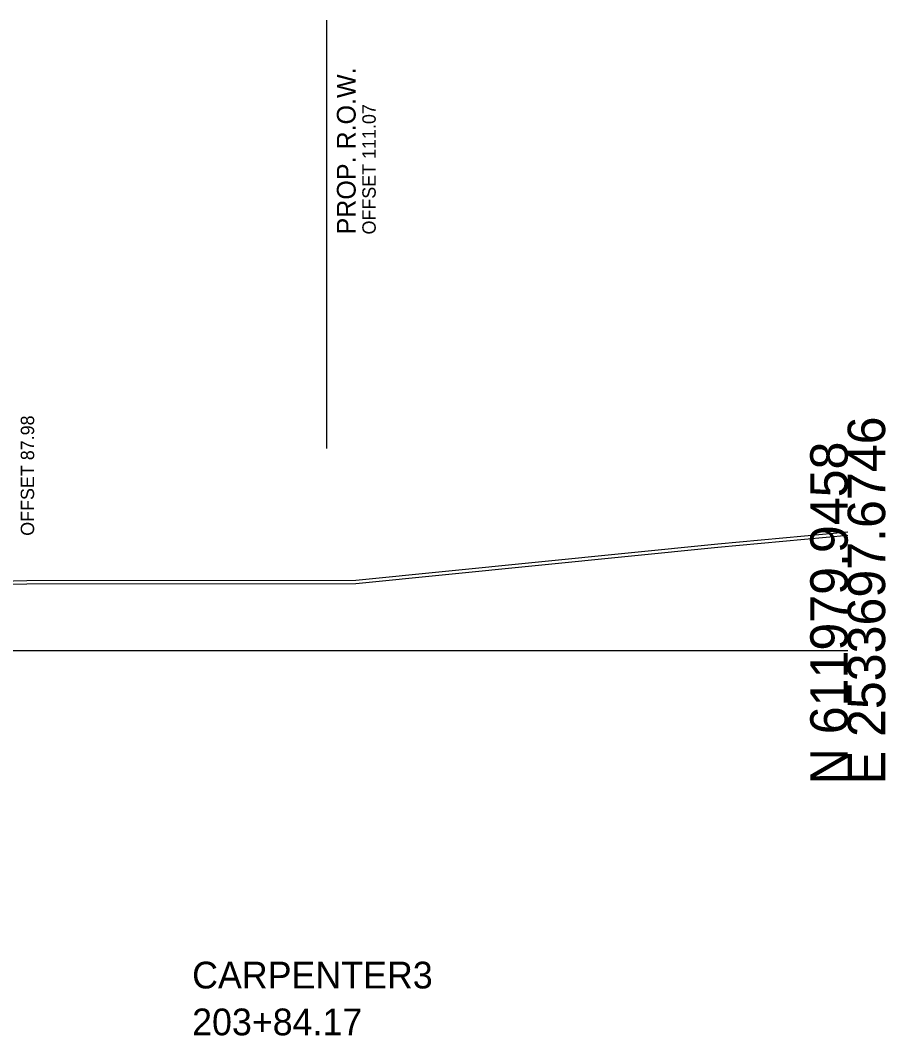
# Model space of a CAD drawing. Extents: x -120 to 2876, y -25 to 8560.
# Drawn here: x 1538.2 to 1602.8, y 1471.2 to 1547.1 of the extents above; entities that cross this region are included whole.
import ezdxf

# ---------------------------------------------------------------- set-up
doc = ezdxf.new("R2010")
doc.units = 0
for name, color, linetype in [('DESIGN - ROW - Right-of-Way and Easement Labels', 7, 'Continuous'), ('DESIGN - ROW - Right-of-Way Linework', 7, 'Continuous'), ('DESIGN - SHEET - Light Grid', 7, 'Continuous'), ('DESIGN - TYPICAL - Slope Tie Text', 7, 'Continuous'), ('DESIGN - TYPICAL - Warning Text', 7, 'Continuous'), ('SURVEY - GROUND - Bottom of Topsoil Layer', 7, 'Continuous'), ('SURVEY - GROUND - Top of Ground', 7, 'Continuous')]:
    doc.layers.add(name, color=color, linetype=linetype)

msp = doc.modelspace()

# ---------------------------------------------------------------- linework, layer by layer
at = {"layer": 'DESIGN - ROW - Right-of-Way Linework'}
msp.add_line((1561.071, 1515.084), (1561.071, 1547.084), dxfattribs=at)
at = {"layer": 'DESIGN - SHEET - Light Grid'}
msp.add_line((1450, 1500), (1600, 1500), dxfattribs=at)
at = {"layer": 'SURVEY - GROUND - Bottom of Topsoil Layer'}
for p, q in [((1590.297, 1507.713), (1600, 1508.625)), ((1563.24, 1504.998), (1590.297, 1507.713)), ((1522.638, 1504.585), (1538.647, 1504.987)), ((1538.647, 1504.987), (1563.24, 1504.998))]:
    msp.add_line(p, q, dxfattribs=at)
at = {"layer": 'SURVEY - GROUND - Top of Ground'}
msp.add_lwpolyline([(1473.864, 1514.234), (1475.077, 1514.18), (1478.118, 1514.044), (1478.454, 1514.007), (1480.584, 1513.775), (1481.765, 1513.702), (1493.104, 1506.549), (1502.402, 1501.51), (1506.283, 1501.499), (1508.714, 1501.381), (1509.622, 1502.095), (1512.504, 1504.244), (1522.638, 1504.835), (1538.647, 1505.237), (1563.24, 1505.248), (1590.297, 1507.963), (1600, 1508.875)], dxfattribs=at)

# ---------------------------------------------------------------- texts
at = {"layer": 'DESIGN - ROW - Right-of-Way and Easement Labels'}
for s, height, p in [('PROP. R.O.W.', 1.4, (1563.221, 1531.084)), ('OFFSET 111.07', 1, (1564.721, 1531.084))]:
    msp.add_text(s, height=height, rotation=90, dxfattribs=at).set_placement(p)
at = {"layer": 'DESIGN - SHEET - Light Grid'}
for s, p in [('E 2533697.6746', (1602.8, 1490)), ('N 611979.9458', (1600, 1490))]:
    msp.add_text(s, height=2.8, rotation=90, dxfattribs=at).set_placement(p)
at = {"layer": 'DESIGN - TYPICAL - Slope Tie Text'}
msp.add_text('OFFSET 87.98', height=1, rotation=90, dxfattribs=at).set_placement((1539.19, 1508.571))
at = {"layer": 'DESIGN - TYPICAL - Warning Text'}
for s, p in [('CARPENTER3', (1551, 1474.75)), ('203+84.17', (1551, 1471.25))]:
    msp.add_text(s, height=2, dxfattribs=at).set_placement(p)

doc.saveas('drawing.dxf')
